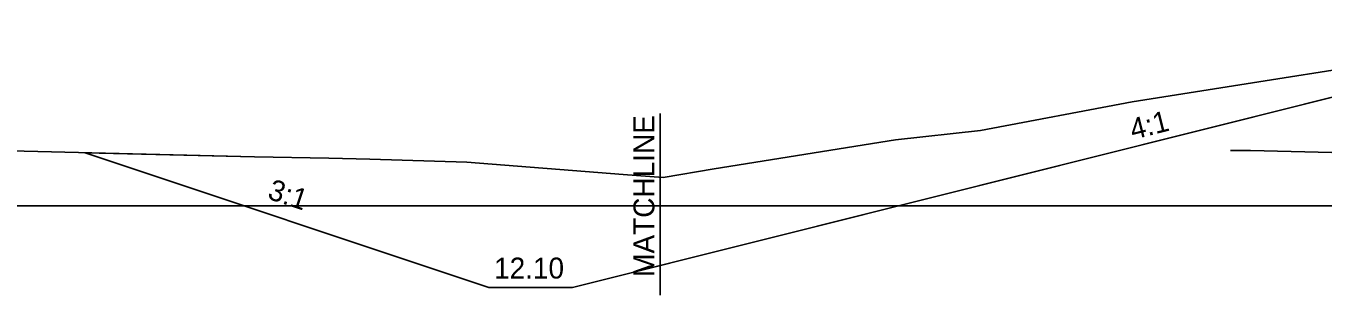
# Model space of a CAD drawing. Extents: x 2207892 to 2209721, y 61220 to 65449.
# Drawn here: x 2207992.8 to 2208054.9, y 61403 to 61415.9 of the extents above; entities that cross this region are included whole.
import ezdxf

# ---------------------------------------------------------------- set-up
doc = ezdxf.new("R2010")
doc.units = 0
for name, color, linetype in [('Exist DTM Breakline Cogo Comment', 7, 'Continuous'), ('Exist DTM Breakline Cogo Elevation', 7, 'Continuous'), ('Exist DTM Breakline Underwater Cogo Comment', 7, 'Continuous'), ('Exist Hydro Stream or Body of Water Cogo Elevation', 7, 'Continuous'), ('Exist Roads EOP Other Cogo Elevation', 7, 'Continuous'), ('Exist Roads EOP Other Cogo Number', 7, 'Continuous')]:
    doc.layers.add(name, color=color, linetype=linetype)

msp = doc.modelspace()

# ---------------------------------------------------------------- linework, layer by layer
at = {"layer": 'Exist DTM Breakline Cogo Comment'}
msp.add_lwpolyline([(2207995.655, 61409.848), (2208003.745, 61409.652), (2208007.314, 61409.588), (2208009.269, 61409.538), (2208013.913, 61409.4), (2208021.398, 61408.805), (2208023.303, 61408.662), (2208025.751, 61409.074), (2208034.425, 61410.458), (2208038.505, 61410.914), (2208045.753, 61412.276), (2208062.337, 61414.894), (2208063.212, 61414.929), (2208063.558, 61414.95), (2208065.403, 61415.053), (2208065.593, 61415.067), (2208018.968, 61403.41), (2208014.968, 61403.41)], close=True, dxfattribs=at)
at = {"layer": 'Exist DTM Breakline Cogo Elevation'}
msp.add_line((2208023.174, 61403.047), (2208023.174, 61411.718), dxfattribs=at)
msp.add_lwpolyline([(2208050.47, 61409.955), (2208051.421, 61409.95), (2208063.745, 61409.652), (2208067.314, 61409.588), (2208069.269, 61409.538), (2208073.913, 61409.4), (2208081.398, 61408.805), (2208083.174, 61408.671)], dxfattribs=at)
at = {"layer": 'Exist Hydro Stream or Body of Water Cogo Elevation'}
for p, q in [((2208068.931, 61415.901), (2208018.968, 61403.41)), ((2208014.968, 61403.41), (2207995.655, 61409.848)), ((2208018.968, 61403.41), (2208014.968, 61403.41))]:
    msp.add_line(p, q, dxfattribs=at)
at = {"layer": 'Exist Roads EOP Other Cogo Elevation'}
msp.add_lwpolyline([(2207991.421, 61409.95), (2208003.745, 61409.652), (2208007.314, 61409.588), (2208009.269, 61409.538), (2208013.913, 61409.4), (2208021.398, 61408.805), (2208023.303, 61408.662), (2208025.751, 61409.074), (2208034.425, 61410.458), (2208038.505, 61410.914), (2208045.753, 61412.276), (2208062.337, 61414.894)], dxfattribs=at)
at = {"layer": 'Exist Roads EOP Other Cogo Number'}
msp.add_line((2207918.174, 61407.31), (2208118.174, 61407.31), dxfattribs=at)

# ---------------------------------------------------------------- texts
at = {"layer": 'Exist DTM Breakline Cogo Elevation'}
msp.add_text('MATCHLINE', height=1, rotation=90, dxfattribs=at).set_placement((2208022.89, 61403.915))
at = {"layer": 'Exist DTM Breakline Underwater Cogo Comment'}
for s, rotation, p in [('4:1', 14.03624, (2208045.793, 61410.462)), ('3:1', 341.56505, (2208004.325, 61407.665))]:
    msp.add_text(s, height=1, rotation=rotation, dxfattribs=at).set_placement(p)
msp.add_text('12.10', height=1, dxfattribs=at).set_placement((2208015.221, 61403.834))

doc.saveas('drawing.dxf')
